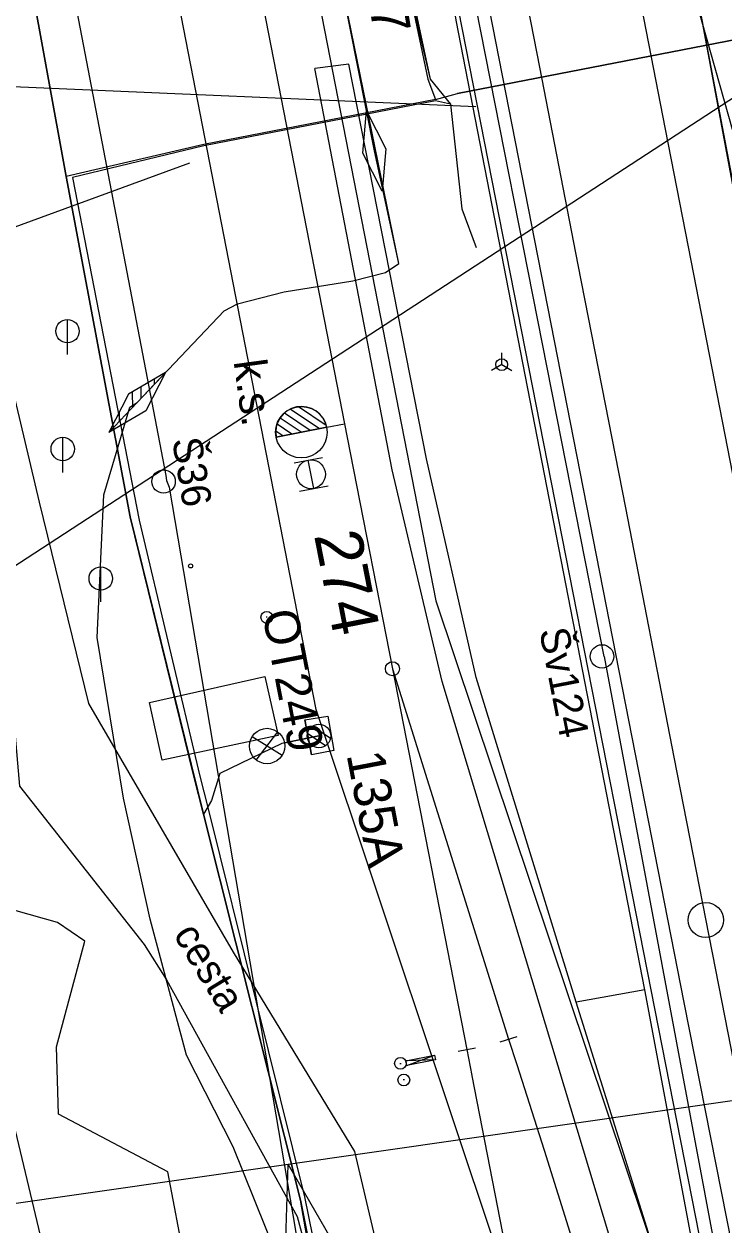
# Model space of a CAD drawing. Extents: x -545846 to -545044, y -1122650 to -1119108.
# Drawn here: x -545692.9 to -545663.1, y -1119489.2 to -1119438 of the extents above; entities that cross this region are included whole.
import ezdxf

# ---------------------------------------------------------------- set-up
doc = ezdxf.new("R2010")
doc.units = 0
for name, color, linetype in [('osvětlené plochy-hodnota-obrys', 7, 'Continuous'), ('Vrstva 1', 7, 'Continuous'), ('Vrstva 1 - Koleje', 7, 'Continuous'), ('Vrstva 11 - Trakce', 7, 'Continuous'), ('Vrstva 12 - Trakce zaklady', 7, 'Continuous'), ('Vrstva 19 - Staniceni', 7, 'Continuous'), ('Vrstva 2', 7, 'Continuous'), ('Vrstva 23', 7, 'Continuous'), ('Vrstva 25', 7, 'Continuous'), ('Vrstva 26', 7, 'Continuous'), ('Vrstva 28', 7, 'Continuous'), ('Vrstva 28 - zabzar', 7, 'Continuous'), ('Vrstva 3', 7, 'Continuous'), ('Vrstva 3 - Lisy - Pocitaci body', 7, 'Continuous'), ('Vrstva 31', 7, 'Continuous'), ('Vrstva 32', 7, 'Continuous'), ('Vrstva 35', 7, 'Continuous'), ('Vrstva 4 - Teren - stezky - prechody - plochy', 7, 'Continuous'), ('Vrstva 43', 7, 'Continuous'), ('Vrstva 44', 7, 'Continuous'), ('Vrstva 49', 7, 'Continuous'), ('Vrstva 51', 7, 'Continuous'), ('Vrstva 59', 7, 'Continuous'), ('Vrstva 63', 7, 'Continuous'), ('Vrstva 7 - Namezniky-vystroj', 7, 'Continuous')]:
    doc.layers.add(name, color=color, linetype=linetype)

msp = doc.modelspace()

# ---------------------------------------------------------------- linework, layer by layer
at = {"layer": 'osvětlené plochy-hodnota-obrys'}
for points in [[(-545664.282, -1119515.639), (-545680.447, -1119467.233), (-545736.202, -1119180.74), (-545730.573, -1119179.645)], [(-545730.573, -1119179.645), (-545675.345, -1119462.605), (-545660.82, -1119505.941)], [(-545716.386, -1119223.717), (-545705.994, -1119221.66), (-545669.439, -1119408.759), (-545659.4, -1119462.635), (-545647.69, -1119521.347), (-545640.519, -1119558.729), (-545633.585, -1119589.698), (-545629.517, -1119613.814), (-545623.042, -1119645.057), (-545619.034, -1119667.556), (-545607.519, -1119727.517)], [(-545610.895, -1119760.665), (-545622.836, -1119699.488), (-545637.26, -1119626.872), (-545653.542, -1119543.449), (-545716.386, -1119223.717)]]:
    msp.add_lwpolyline(points, dxfattribs=at)
at = {"layer": 'Vrstva 1'}
for points in [[(-545684.113, -1119430.211), (-545684.113, -1119430.211), (-545682.598, -1119437.849), (-545679.241, -1119455.056), (-545679.007, -1119456.293), (-545677.202, -1119465.493), (-545674.031, -1119481.718), (-545673.813, -1119482.835)], [(-545677.202, -1119465.493), (-545672.247, -1119481.282), (-545671.898, -1119482.365)]]:
    msp.add_lwpolyline(points, dxfattribs=at)
at = {"layer": 'Vrstva 1 - Koleje'}
for points in [[(-545683.274, -1119376.56), (-545681.242, -1119386.97), (-545679.47, -1119396.069), (-545677.244, -1119407.477), (-545675.184, -1119418.032), (-545673.045, -1119429.027), (-545670.931, -1119439.856), (-545669.293, -1119448.281), (-545667.274, -1119458.644), (-545665.203, -1119469.256), (-545663.032, -1119480.361), (-545661.358, -1119488.941), (-545659.379, -1119499.086)], [(-545675.912, -1119389.513), (-545675.759, -1119390.298), (-545671.927, -1119409.919), (-545665.915, -1119431.178), (-545662.323, -1119443.901), (-545656.357, -1119464.982), (-545652.53, -1119484.609), (-545652.377, -1119485.394)], [(-545675.912, -1119389.513), (-545675.759, -1119390.298), (-545674.983, -1119394.269), (-545671.927, -1119409.919), (-545667.706, -1119431.538), (-545665.572, -1119442.504), (-545664.599, -1119447.508), (-545663.149, -1119454.944), (-545661.077, -1119465.581), (-545659.119, -1119475.61), (-545657.219, -1119485.395), (-545655.182, -1119495.829), (-545653.541, -1119504.242), (-545653.037, -1119506.841)], [(-545671.898, -1119482.365), (-545670.736, -1119486.005), (-545668.403, -1119493.448)], [(-545673.811, -1119482.836), (-545671.313, -1119495.675), (-545669.505, -1119504.975), (-545667.947, -1119513.018), (-545662.4, -1119541.424), (-545660.697, -1119551.332), (-545659.275, -1119561.505), (-545658.148, -1119572.104), (-545657.527, -1119582.463), (-545657.339, -1119589.06), (-545656.945, -1119598.604), (-545656.274, -1119608.583), (-545655.31, -1119618.93), (-545654.021, -1119629.341), (-545652.534, -1119639.322), (-545651.124, -1119648.586), (-545649.453, -1119659.616), (-545647.771, -1119670.646), (-545646.146, -1119681.578), (-545645.086, -1119692.159), (-545644.623, -1119702.795), (-545644.886, -1119713.798)]]:
    msp.add_lwpolyline(points, dxfattribs=at)
at = {"layer": 'Vrstva 11 - Trakce'}
for p, q in [((-545680.816, -1119468.246), (-545680.049, -1119468.766)), ((-545680.6, -1119467.94), (-545679.843, -1119468.453))]:
    msp.add_line(p, q, dxfattribs=at)
msp.add_circle((-545680.332, -1119468.358), 0.5, dxfattribs=at)
at = {"layer": 'Vrstva 12 - Trakce zaklady'}
for p, q in [((-545680.933, -1119467.671), (-545679.958, -1119467.52)), ((-545679.692, -1119468.984), (-545680.646, -1119469.167))]:
    msp.add_line(p, q, dxfattribs=at)
for points in [[(-545679.958, -1119467.52), (-545679.692, -1119468.984), (-545680.646, -1119469.167), (-545680.933, -1119467.671), (-545679.958, -1119467.52)], [(-545680.933, -1119467.671), (-545680.933, -1119467.671), (-545680.646, -1119469.167), (-545680.646, -1119469.167)], [(-545679.958, -1119467.52), (-545679.958, -1119467.52), (-545679.692, -1119468.984), (-545679.692, -1119468.984)]]:
    msp.add_lwpolyline(points, dxfattribs=at)
at = {"layer": 'Vrstva 19 - Staniceni'}
msp.add_circle((-545663.845, -1119476.204), 0.75, dxfattribs=at)
at = {"layer": 'Vrstva 2'}
for p, q in [((-545680.701, -1119455.343), (-545681.806, -1119454.599)), ((-545680.311, -1119455.267), (-545681.554, -1119454.43)), ((-545680.02, -1119455.124), (-545681.201, -1119454.328)), ((-545681.482, -1119455.495), (-545682.114, -1119455.07)), ((-545681.092, -1119455.419), (-545681.99, -1119454.814)), ((-545679.997, -1119455.206), (-545679.241, -1119455.056)), ((-545681.873, -1119455.571), (-545682.17, -1119455.372)), ((-545682.153, -1119455.626), (-545679.998, -1119455.205)), ((-545679.998, -1119455.206), (-545682.153, -1119455.626)), ((-545679.998, -1119455.205), (-545679.998, -1119455.206)), ((-545677.202, -1119465.493), (-545672.247, -1119481.282)), ((-545672.606, -1119481.392), (-545671.888, -1119481.172)), ((-545674.399, -1119481.79), (-545673.663, -1119481.646))]:
    msp.add_line(p, q, dxfattribs=at)
msp.add_lwpolyline([(-545679.241, -1119455.056), (-545679.007, -1119456.293), (-545677.202, -1119465.493), (-545674.031, -1119481.718)], dxfattribs=at)
for centre, radius in [((-545681.082, -1119455.416), 1.097), ((-545677.202, -1119465.493), 0.3)]:
    msp.add_circle(centre, radius, dxfattribs=at)
msp.add_arc((-545681.075, -1119455.416), 1.098, 11.0625, 191.0233, dxfattribs=at)
at = {"layer": 'Vrstva 23'}
for p, q in [((-545687.561, -1119466.926), (-545682.639, -1119465.823)), ((-545682.639, -1119465.823), (-545682.075, -1119468.332)), ((-545687.009, -1119469.391), (-545687.561, -1119466.926)), ((-545682.075, -1119468.332), (-545687.009, -1119469.391))]:
    msp.add_line(p, q, dxfattribs=at)
at = {"layer": 'Vrstva 25'}
for p, q in [((-545683.183, -1119468.386), (-545681.899, -1119469.177)), ((-545683.004, -1119469.385), (-545682.091, -1119468.186)), ((-545681.804, -1119468.645), (-545680.332, -1119468.358))]:
    msp.add_line(p, q, dxfattribs=at)
msp.add_circle((-545682.545, -1119468.787), 0.754, dxfattribs=at)
at = {"layer": 'Vrstva 26'}
for points in [[(-545687.063, -1119385.421), (-545684.343, -1119398.043), (-545682.972, -1119406.266), (-545682.725, -1119408.63), (-545682.477, -1119411.005), (-545680.726, -1119416.47), (-545676.513, -1119436.442), (-545675.693, -1119440.376), (-545675.368, -1119441.242), (-545685.239, -1119443.159), (-545691.11, -1119444.524)], [(-545680.794, -1119490.021), (-545681.126, -1119488.142), (-545685.254, -1119471.698), (-545685.659, -1119470.078), (-545688.379, -1119459.015), (-545691.11, -1119444.524), (-545693.485, -1119431.472), (-545696.136, -1119420.308), (-545697.84, -1119411.888), (-545699.458, -1119402.071), (-545701.735, -1119388.211)], [(-545675.368, -1119441.242), (-545674.422, -1119440.976), (-545659.563, -1119438.09), (-545653.772, -1119461.566), (-545654.229, -1119461.646), (-545654.429, -1119461.65)], [(-545659.563, -1119438.09), (-545674.422, -1119440.976)], [(-545675.368, -1119441.242), (-545685.239, -1119443.159)], [(-545680.332, -1119468.358), (-545680.833, -1119468.453), (-545681.916, -1119468.673), (-545684.551, -1119469.952), (-545684.915, -1119471.105), (-545685.254, -1119471.698)], [(-545679.942, -1119493.416), (-545681.764, -1119490.264), (-545681.646, -1119486.626), (-545679.824, -1119489.778), (-545679.942, -1119493.416)]]:
    msp.add_lwpolyline(points, dxfattribs=at)
at = {"layer": 'Vrstva 28'}
for p, q in [((-545682.533, -1119463.301), (-545682.583, -1119463.301)), ((-545676.885, -1119482.311), (-545676.835, -1119482.311)), ((-545676.691, -1119483.019), (-545676.741, -1119483.019))]:
    msp.add_line(p, q, dxfattribs=at)
for centre in [(-545682.558, -1119463.301), (-545676.86, -1119482.311), (-545676.716, -1119483.019)]:
    msp.add_circle(centre, 0.25, dxfattribs=at)
at = {"layer": 'Vrstva 28 - zabzar'}
msp.add_lwpolyline([(-545681.68, -1119491.62), (-545683.99, -1119485.87), (-545685.98, -1119481.96), (-545687.53, -1119476.16), (-545688.66, -1119471.01), (-545689.78, -1119464.16), (-545689.5, -1119458.09), (-545688.39, -1119454.35), (-545688.08, -1119454.15), (-545684.37, -1119450.24), (-545683.81, -1119449.95), (-545681.81, -1119449.43), (-545678.89, -1119448.97), (-545677.49, -1119448.61), (-545676.93, -1119448.23), (-545679.71, -1119434.6)], dxfattribs=at)
at = {"layer": 'Vrstva 3'}
for p, q in [((-545681.395, -1119456.725), (-545680.186, -1119456.486)), ((-545680.552, -1119457.814), (-545680.79, -1119456.606)), ((-545681.156, -1119457.934), (-545679.947, -1119457.695))]:
    msp.add_line(p, q, dxfattribs=at)
msp.add_circle((-545680.672, -1119457.208), 0.616, dxfattribs=at)
at = {"layer": 'Vrstva 3 - Lisy - Pocitaci body'}
for q in [(-545672.543, -1119452.034), (-545672.976, -1119452.784), (-545672.11, -1119452.784)]:
    msp.add_line((-545672.543, -1119452.534), q, dxfattribs=at)
msp.add_circle((-545672.543, -1119452.534), 0.25, dxfattribs=at)
at = {"layer": 'Vrstva 31'}
for points in [[(-545675.08, -1119380.973), (-545677.404, -1119381.86), (-545678.81, -1119382.38), (-545682.029, -1119382.937), (-545685.653, -1119383.563), (-545686.29, -1119382.94), (-545686.991, -1119385.539), (-545684.322, -1119398.039), (-545682.95, -1119406.261), (-545682.441, -1119410.994), (-545680.712, -1119416.465), (-545675.599, -1119440.373), (-545674.73, -1119441.437), (-545675.364, -1119441.292), (-545685.239, -1119443.209), (-545690.839, -1119444.56)], [(-545686.8, -1119383.83), (-545687.063, -1119385.421), (-545684.343, -1119398.043), (-545682.95, -1119406.261), (-545682.477, -1119411.005), (-545680.726, -1119416.47), (-545676.513, -1119436.442), (-545675.599, -1119440.373), (-545674.73, -1119441.437), (-545674.246, -1119445.902), (-545673.636, -1119447.545)], [(-545698.546, -1119386.715), (-545701.735, -1119388.211), (-545697.84, -1119411.888), (-545696.136, -1119420.308), (-545693.485, -1119431.472), (-545691.11, -1119444.524), (-545688.379, -1119459.015), (-545685.254, -1119471.698), (-545681.126, -1119488.142), (-545680.197, -1119492.738)], [(-545681.68, -1119491.62), (-545683.99, -1119485.87), (-545685.98, -1119481.96), (-545687.53, -1119476.16), (-545688.66, -1119471.01), (-545689.78, -1119464.16), (-545689.5, -1119458.09), (-545688.39, -1119454.35), (-545688.08, -1119454.15), (-545684.37, -1119450.24), (-545683.81, -1119449.95), (-545681.81, -1119449.43), (-545678.89, -1119448.97), (-545677.49, -1119448.61), (-545676.93, -1119448.23), (-545677.97, -1119443.43), (-545679.71, -1119434.6)], [(-545677.632, -1119445.147), (-545678.461, -1119443.527), (-545678.308, -1119441.713), (-545677.479, -1119443.333), (-545677.632, -1119445.147)], [(-545674.73, -1119441.437), (-545674.246, -1119445.902), (-545673.636, -1119447.545)], [(-545690.839, -1119444.56), (-545687.993, -1119459.166), (-545685.404, -1119470.078), (-545685.069, -1119471.412), (-545680.946, -1119487.997), (-545680.08, -1119492.264), (-545677.962, -1119500.397), (-545676.007, -1119508.211), (-545673.637, -1119519.489), (-545670.181, -1119535.446), (-545668.263, -1119543.914), (-545667.463, -1119548.89), (-545667.286, -1119550.826), (-545666.571, -1119553.151), (-545664.456, -1119553.497)]]:
    msp.add_lwpolyline(points, dxfattribs=at)
at = {"layer": 'Vrstva 32'}
for p, q in [((-545686.993, -1119452.952), (-545687.004, -1119453.016)), ((-545687.93, -1119453.491), (-545687.918, -1119453.979)), ((-545687.361, -1119453.155), (-545687.354, -1119453.385)), ((-545688.297, -1119453.719), (-545688.281, -1119454.361)), ((-545688.854, -1119454.569), (-545688.843, -1119454.954)), ((-545689.196, -1119455.246), (-545689.193, -1119455.323))]:
    msp.add_line(p, q, dxfattribs=at)
for points in [[(-545681.68, -1119491.62), (-545683.99, -1119485.87), (-545685.98, -1119481.96), (-545687.53, -1119476.16), (-545688.66, -1119471.01), (-545689.78, -1119464.16), (-545689.5, -1119458.09), (-545688.39, -1119454.35), (-545688.08, -1119454.15), (-545684.37, -1119450.24), (-545683.81, -1119449.95), (-545681.81, -1119449.43), (-545678.89, -1119448.97), (-545677.49, -1119448.61), (-545676.93, -1119448.23), (-545679.71, -1119434.6), (-545680.78, -1119428.7), (-545683.44, -1119416.1), (-545684.36, -1119411.01), (-545685.82, -1119403.23), (-545686.73, -1119397.61), (-545689.13, -1119385.55), (-545692.02, -1119370.12)], [(-545686.867, -1119452.872), (-545687.711, -1119454.5), (-545689.293, -1119455.428)]]:
    msp.add_lwpolyline(points, dxfattribs=at)
msp.add_lwpolyline([(-545686.867, -1119452.872), (-545688.449, -1119453.8), (-545689.293, -1119455.428)], close=True, dxfattribs=at)
at = {"layer": 'Vrstva 35'}
msp.add_lwpolyline([(-545683.81, -1119449.95), (-545681.81, -1119449.43), (-545678.89, -1119448.97), (-545677.49, -1119448.61)], dxfattribs=at)
at = {"layer": 'Vrstva 4 - Teren - stezky - prechody - plochy'}
for points in [[(-545663.732, -1119493.482), (-545662.217, -1119493.136), (-545662.27, -1119492.38), (-545664.76, -1119479.724), (-545673.059, -1119437.391), (-545683.638, -1119382.878), (-545688.896, -1119355.974), (-545694.44, -1119327.554), (-545697.827, -1119310.185), (-545704.93, -1119274.138), (-545706.059, -1119274.463)], [(-545663.732, -1119493.482), (-545663.86, -1119492.962), (-545666.439, -1119479.174), (-545674.481, -1119437.861), (-545674.838, -1119435.68), (-545679.752, -1119410.669), (-545685.159, -1119383.219), (-545690.428, -1119356.383), (-545695.755, -1119327.999), (-545699.195, -1119310.645), (-545701.333, -1119300.523), (-545702.296, -1119295.62), (-545704.229, -1119285.397), (-545706.059, -1119274.463)], [(-545664.359, -1119496.038), (-545664.586, -1119495.186), (-545665.53, -1119491.933), (-545669.372, -1119479.709), (-545673.63, -1119465.87), (-545675.753, -1119456.543), (-545679.064, -1119439.733), (-545680.512, -1119439.909)], [(-545664.359, -1119496.038), (-545665.883, -1119496.457), (-545666.229, -1119495.71), (-545667.132, -1119492.419), (-545675.08, -1119466.035), (-545677.215, -1119457.024), (-545680.512, -1119439.909)], [(-545666.439, -1119479.174), (-545669.372, -1119479.709)]]:
    msp.add_lwpolyline(points, dxfattribs=at)
at = {"layer": 'Vrstva 43'}
for p, q in [((-545691.052, -1119452.109), (-545691.052, -1119450.611)), ((-545691.252, -1119457.13), (-545691.252, -1119455.632)), ((-545689.633, -1119462.648), (-545689.633, -1119461.15))]:
    msp.add_line(p, q, dxfattribs=at)
for centre, radius in [((-545691.052, -1119451.109), 0.498), ((-545691.252, -1119456.13), 0.498), ((-545686.954, -1119457.515), 0.5), ((-545689.633, -1119461.648), 0.498), ((-545668.268, -1119464.969), 0.5)]:
    msp.add_circle(centre, radius, dxfattribs=at)
at = {"layer": 'Vrstva 44'}
for points in [[(-545698.387, -1119332.167), (-545688.892, -1119380.643), (-545688.773, -1119381.07), (-545688.658, -1119381.436), (-545684.204, -1119404.98), (-545684.3, -1119405.214), (-545684.473, -1119405.424), (-545695.821, -1119407.408), (-545696.222, -1119407.647), (-545696.303, -1119408.062), (-545686.856, -1119457.258), (-545686.828, -1119457.471), (-545686.717, -1119457.756), (-545678.249, -1119507.566)], [(-545659.224, -1119462.954), (-545669.377, -1119409.578), (-545676.105, -1119375.826)], [(-545668.174, -1119464.967), (-545678.695, -1119411.658), (-545685.683, -1119377.701), (-545685.693, -1119377.451)], [(-545668.174, -1119464.967), (-545658.965, -1119514.134), (-545649.325, -1119561.814), (-545649.25, -1119561.916)]]:
    msp.add_lwpolyline(points, dxfattribs=at)
at = {"layer": 'Vrstva 49'}
for points in [[(-545682.12, -1119531.061), (-545685.034, -1119518.688), (-545687.449, -1119508.219), (-545690.437, -1119497.046), (-545693.269, -1119485.17), (-545694.097, -1119482.564), (-545695.238, -1119478.707), (-545696.352, -1119474.573), (-545696.62, -1119474.508), (-545697.444, -1119469.014), (-545700.602, -1119456.611), (-545703.048, -1119442.937), (-545706.889, -1119429.536), (-545709.808, -1119420.538), (-545710.768, -1119417.661)], [(-545676.868, -1119531.147), (-545679.56, -1119516.912), (-545680.639, -1119507.712), (-545685.33, -1119494.543), (-545686.774, -1119486.935), (-545691.429, -1119484.475), (-545691.514, -1119481.605), (-545690.305, -1119477.101), (-545691.48, -1119476.304), (-545694.464, -1119475.472), (-545694.413, -1119473.018), (-545694.567, -1119472.933), (-545696.943, -1119458.566), (-545698.662, -1119449.742), (-545701.178, -1119439.542), (-545704.615, -1119426.648), (-545707.854, -1119417.767), (-545710.768, -1119417.661)]]:
    msp.add_lwpolyline(points, dxfattribs=at)
at = {"layer": 'Vrstva 51'}
for points in [[(-545700.486, -1119424.952), (-545703.203, -1119425.654), (-545698.84, -1119443.295), (-545695.243, -1119459.09), (-545693.492, -1119465.904), (-545693.089, -1119470.496), (-545687.785, -1119477.251), (-545686.835, -1119478.755), (-545681.263, -1119488.831), (-545678.977, -1119497.29), (-545676.424, -1119511.559), (-545674.568, -1119521.475), (-545673.01, -1119532.044), (-545666.562, -1119530.295)], [(-545666.562, -1119530.295), (-545669.427, -1119521.482), (-545674.009, -1119510.042), (-545676.099, -1119497.534), (-545678.798, -1119486.06), (-545683.97, -1119477.568), (-545690.144, -1119466.972), (-545692.246, -1119458.396), (-545695.995, -1119442.587), (-545700.486, -1119424.952)]]:
    msp.add_lwpolyline(points, dxfattribs=at)
at = {"layer": 'Vrstva 59'}
msp.add_circle((-545685.805, -1119461.113), 0.0873, dxfattribs=at)
at = {"layer": 'Vrstva 63'}
for p, q in [((-545658.91, -1119438.714), (-545708.862, -1119471.264)), ((-545673.644, -1119441.543), (-545715.029, -1119439.755)), ((-545685.853, -1119443.95), (-545712.316, -1119453.615)), ((-545614.243, -1119476.951), (-545705.196, -1119489.997))]:
    msp.add_line(p, q, dxfattribs=at)
at = {"layer": 'Vrstva 7 - Namezniky-vystroj'}
msp.add_line((-545675.362, -1119482.159), (-545676.628, -1119482.201), dxfattribs=at)
msp.add_lwpolyline([(-545676.589, -1119482.398), (-545675.401, -1119481.962), (-545675.362, -1119482.159), (-545676.589, -1119482.398), (-545676.628, -1119482.201), (-545675.401, -1119481.962)], dxfattribs=at)

# ---------------------------------------------------------------- texts
at = {"layer": 'Vrstva 11 - Trakce'}
for s, rotation, p in [('137', 279.2926, (-545678.558, -1119434.988)), ('135A', 280.86, (-545679.162, -1119469.152))]:
    msp.add_text(s, height=1.6, rotation=rotation, dxfattribs=at).set_placement(p)
at = {"layer": 'Vrstva 2'}
msp.add_text('274', height=2, rotation=281.0429, dxfattribs=at).set_placement((-545680.545, -1119459.8))
at = {"layer": 'Vrstva 25'}
msp.add_text('OT249', height=1.5, rotation=281.0428, dxfattribs=at).set_placement((-545682.758, -1119463.111))
at = {"layer": 'Vrstva 43'}
for s, rotation, p in [('Š36', 279.317, (-545686.595, -1119455.733)), ('Šv124', 280.9998, (-545670.948, -1119463.861))]:
    msp.add_text(s, height=1.25, rotation=rotation, dxfattribs=at).set_placement(p)
at = {"layer": 'Vrstva 51'}
msp.add_text('cesta', height=1.25, rotation=301.3432, dxfattribs=at).set_placement((-545686.566, -1119476.819))
at = {"layer": 'Vrstva 63'}
msp.add_text('k.s.', height=1.3705, rotation=277.818, dxfattribs=at).set_placement((-545683.974, -1119452.395))
msp.add_text('k.s.', height=1.3705, rotation=277.818, dxfattribs=at).set_placement((-545683.974, -1119452.395))

doc.saveas('drawing.dxf')
